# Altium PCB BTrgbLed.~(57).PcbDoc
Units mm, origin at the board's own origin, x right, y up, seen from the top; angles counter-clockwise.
Board outline 98.71 x 98.67 mm, 2 copper layers (Top Layer, Bottom Layer); 15 components, 12 nets, 66 pads, 4 vias.
Unrouted connection lines stored in the file: 35.
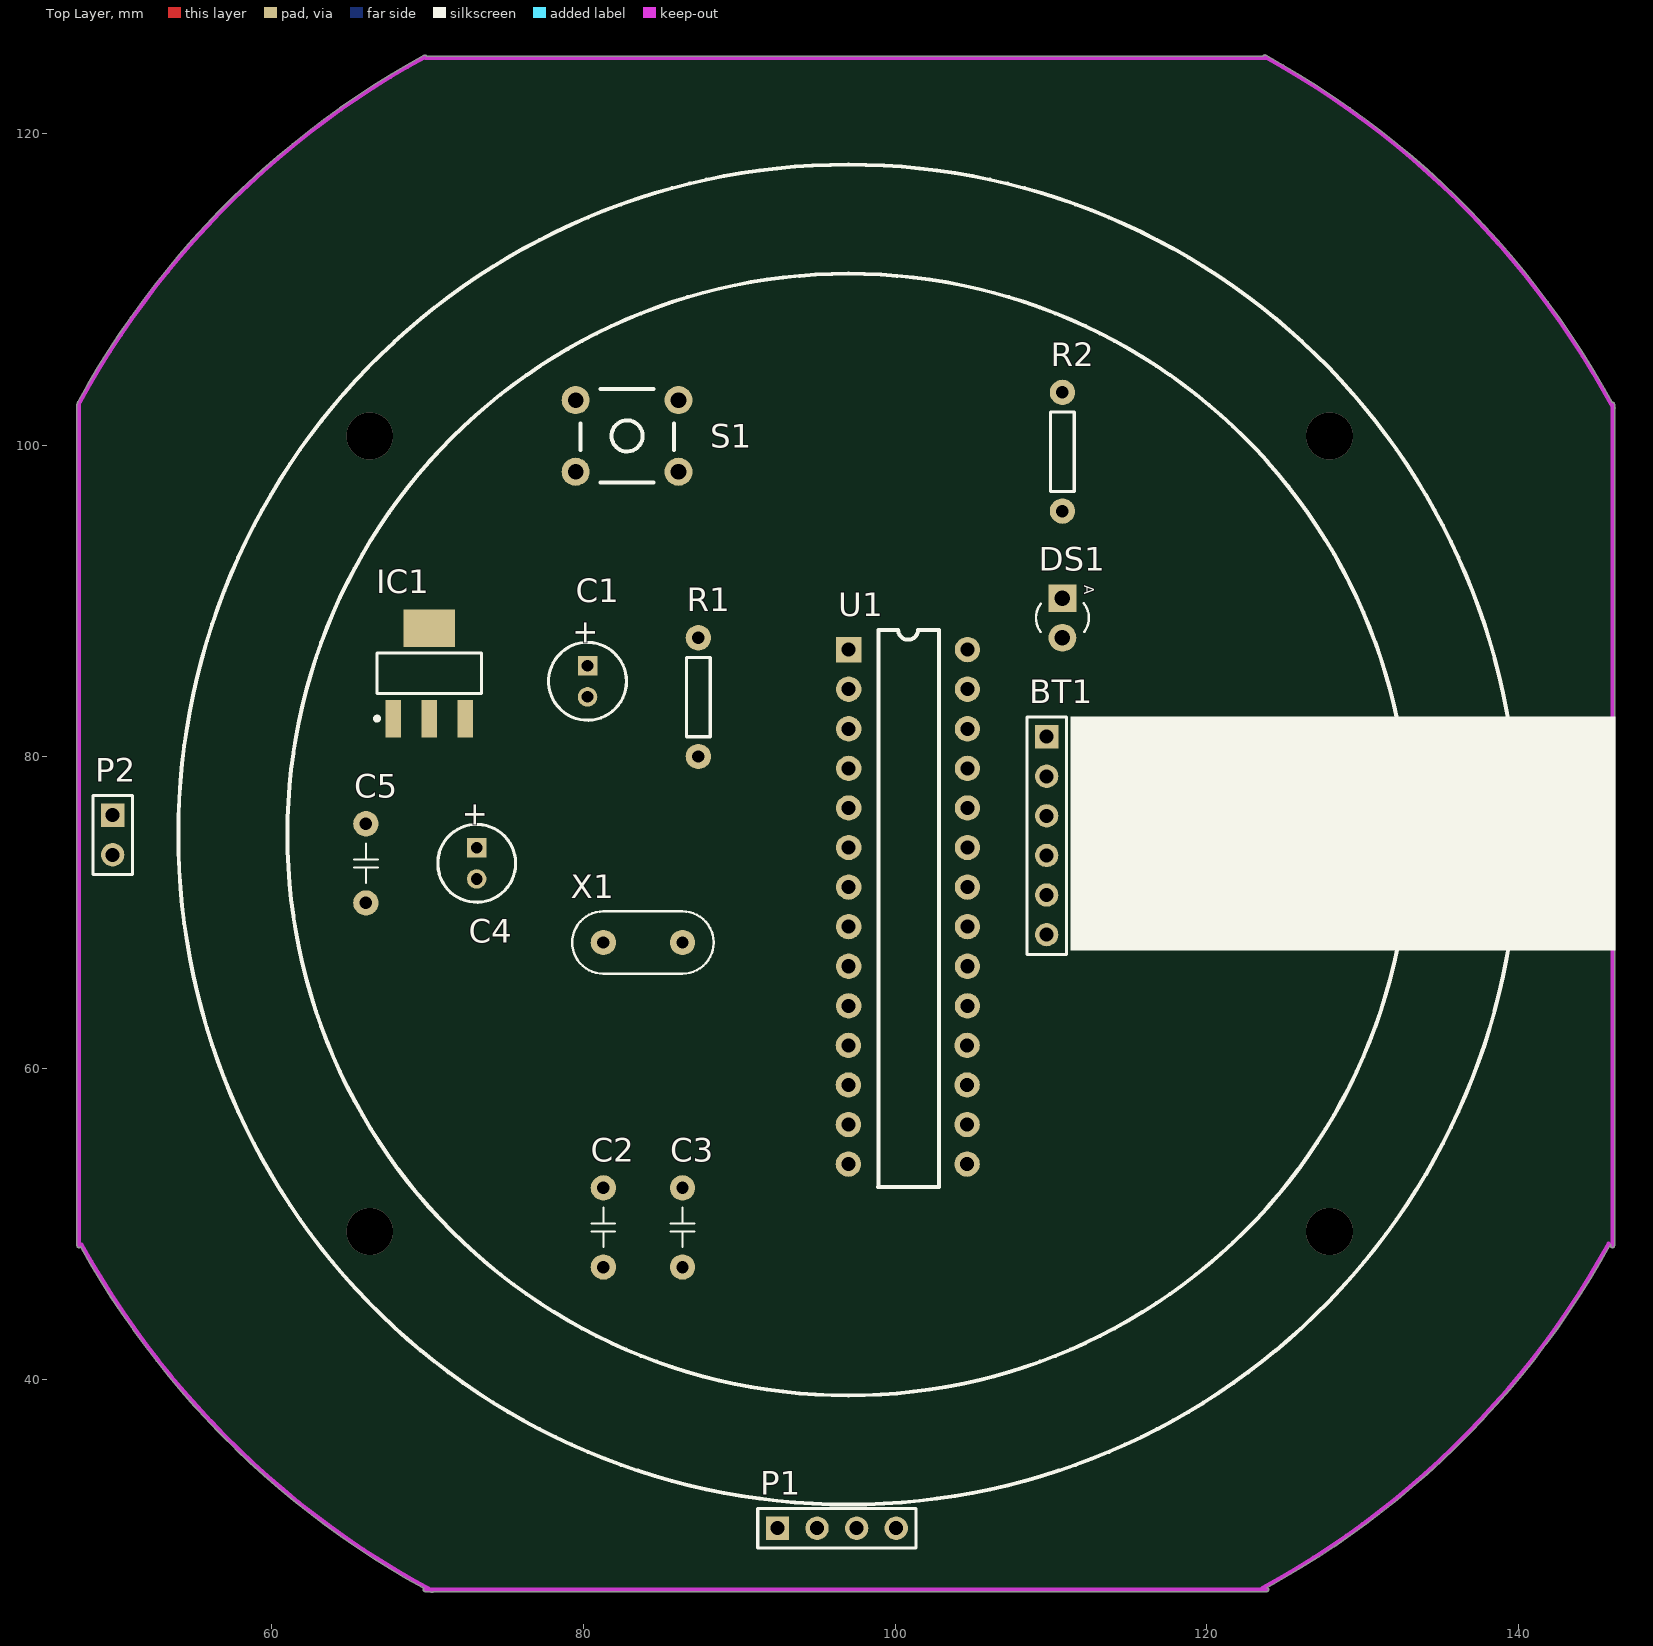
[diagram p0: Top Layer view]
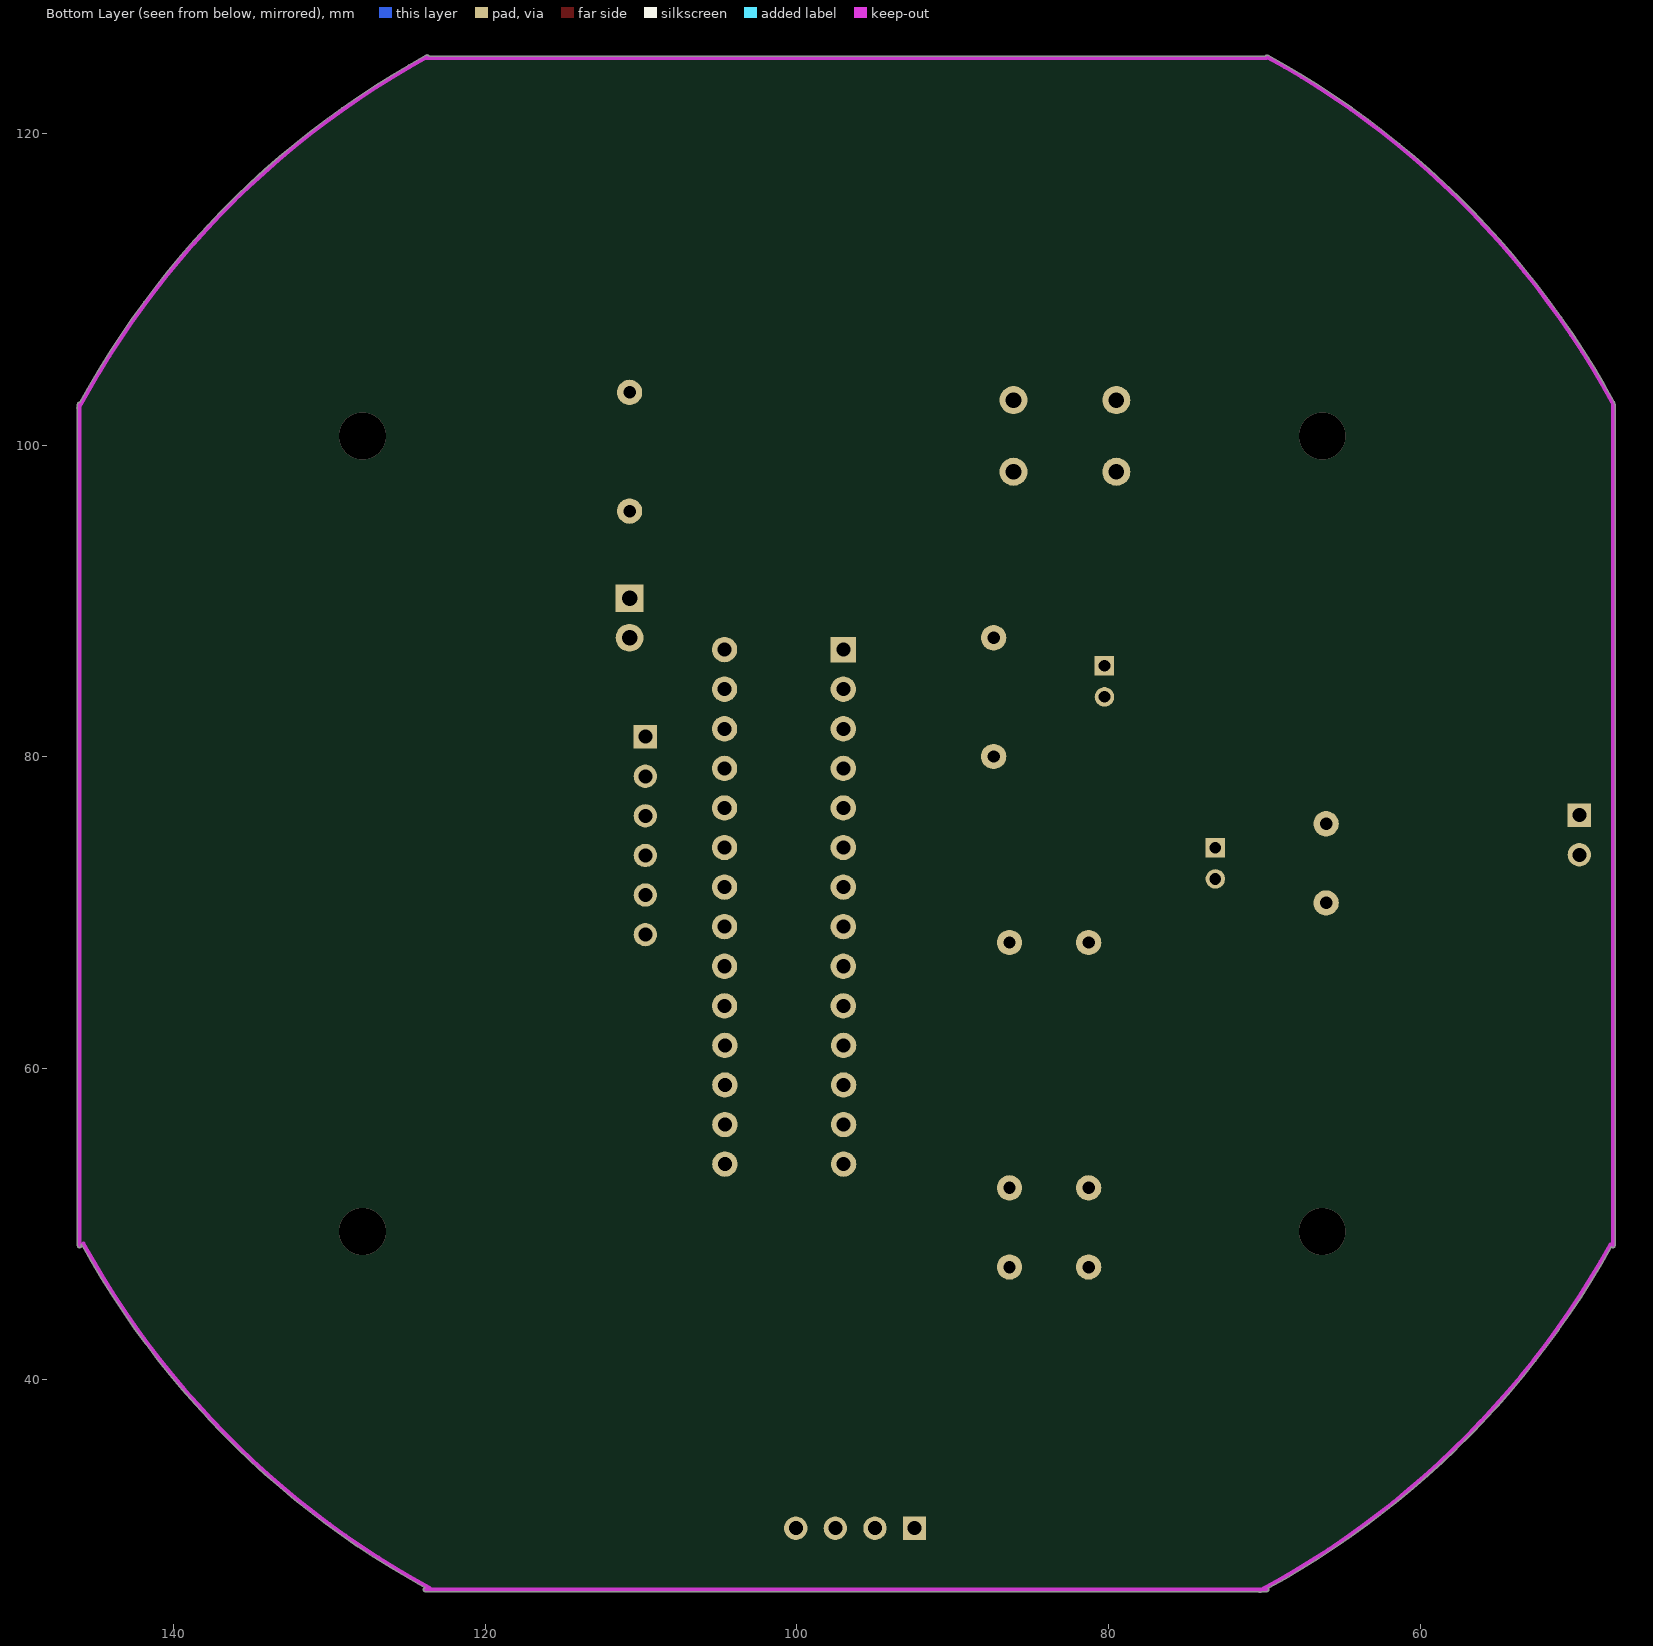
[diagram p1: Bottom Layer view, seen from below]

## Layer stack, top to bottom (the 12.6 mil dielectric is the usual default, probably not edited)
Top Layer: signal copper 0.0356
Dielectric: dielectric 0.32, FR-4, Dk 4.8
Bottom Layer: signal copper 0.0356

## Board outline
69.85,26.416 70.143,26.416 ccw(c96.781,75.819) 70.218,26.375 ccw(c70.279,26.487) 70.384,26.416 123.85,26.416 ccw(c123.85,26.543) 123.977,26.543 ccw(c123.85,26.543) 123.88,26.667 ccw(c96.781,75.819) 145.916,48.69 ccw(c145.805,48.751) 145.923,48.703 145.923,48.616 ccw(c146.05,48.616) 146.177,48.616 146.177,102.295 ccw(c146.082,102.379) 146.209,102.379 ccw(c146.082,102.379) 146.194,102.44 ccw(c96.781,75.819) 146.177,102.47 146.177,102.616 ccw(c146.05,102.616) 146.03,102.742 ccw(c96.781,75.819) 123.795,125.018 ccw(c123.734,124.906) 123.623,124.968 69.925,124.968 ccw(c69.817,124.9) 69.756,125.012 ccw(c96.781,75.819) 47.559,102.791 ccw(c47.671,102.73) 47.544,102.715 ccw(c47.625,102.616) 47.498,102.616 47.498,48.616 ccw(c47.625,48.616) 47.728,48.541 ccw(c96.781,75.819) 69.754,26.627 ccw(c69.85,26.543)

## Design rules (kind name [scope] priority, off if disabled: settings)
Clearance 舖銅安全間距 [All] p1: gap=0.635
Clearance [All] p2: gap=0.254
PolygonConnect [All] p1: connectstyle=Relief reliefconductorwidth=0.254 reliefentries=4 polygonreliefangle="90 Angle"
RoutingLayers [All] p1: top layer_v5=FALSE bottom layer_v5=TRUE
RoutingVias [All] p1: holewidth=0.711 width=1.27 viastyle="Through Hole" minholewidth=0.711 minwidth=1.27 maxholewidth=0.711 maxwidth=1.27
SilkscreenOverComponentPads [All] p1: minsilkscreentomaskgap=0.254
SolderMaskExpansion [All] p1: expansion=0.102
Width [All] p1: maxlimit=1.016 minlimit=0.508 preferedwidth=0.762
26 further rules are at their usual default settings.

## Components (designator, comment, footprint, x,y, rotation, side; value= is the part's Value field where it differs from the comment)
BT1 "Bluetooth" Bluetooth 109.728,81.28 r270 top
C1 "47uF" CAPPR2-5x6.8 80.264,84.836 r270 top
C2 "22pF" C200 81.28,49.784 r0 top
C3 "22pF" C200 86.36,49.784 r0 top
C4 "47uF" CAPPR2-5x6.8 73.152,73.152 r270 top
C5 "100pF" C200 66.04,73.152 r180 top
DS1 "TX-LED" LED-3mm_G 110.744,88.9 r270 top
IC1 "AM1117-5V" SOT-223 70.104,85.344 r90 top
P1 "環形LED燈" HDR1X4 92.456,30.48 r0 top
P2 "12V" HDR1X2 49.784,76.243 r270 top
R1 "10k" AXIAL-0.3 87.376,83.82 r90 top
R2 "220" AXIAL-0.3 110.744,99.568 r90 top
S1 "SW-PB" TACK6 82.804,100.584 r180 top
U1 "ATmega328" DIP-28 97.028,86.868 r270 top
X1 "16MHz" XTAL4-8 83.82,68.072 r180 top

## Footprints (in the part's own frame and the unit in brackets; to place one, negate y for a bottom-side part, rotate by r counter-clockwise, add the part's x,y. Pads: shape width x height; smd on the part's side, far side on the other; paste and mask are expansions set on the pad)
AXIAL-0.3 [mil] "0.3\" Resistor; 2 Leads"
  round 64 hole 31.5: 1(-150,0) 2(150,0)
  silkscreen extent -100,-30 100,30, body extent -161,-39 165,39, height 86
Bluetooth [mm]
  rect 1.5x1.5 hole 0.9: 1(0,0)
  round 1.5 hole 0.9: 2(2.54,0) 3(5.08,0) 4(7.62,0) 5(10.16,0) 6(12.7,0)
  silkscreen extent -1.27,-1.27 13.97,1.27, body extent -1.25,-1.3 13.97,1.28, height 11
C200 [mil] "塑膠電容器"
  round 64 hole 31.5: 1(0,100) 2(0,-100)
  silkscreen extent -30,-50 30,50, body extent -41,-136 39,135, height 354
CAPPR2-5x6.8 [mm] "Capacitor, Electrolytic, Radial; Body 5 x 6.8 mm (Dia.xH typ); Pin Spacing 2 mm (typ)"
  rect 1.25x1.25 hole 0.75: 1(-1,0)
  round 1.25 hole 0.75: 2(1,0)
  silkscreen extent -2.5,-2.5 2.5,2.5
DIP-28 [mil]
  rect 64x64 hole 35.43: 1(0,0)
  round 64 hole 35.43: 2(100,0) 3(200,0) 4(300,0) 5(400,0) 6(500,0) 7(600,0) 8(700,0) 9(800,0) 10(900,0) 11(1000,-0.79) 12(1100,-0.79) 13(1200,-0.79) 14(1300,-0.79) 15(1300,299.21) 16(1200,299.21) 17(1100,299.21) 18(1000,299.21) 19(900,300) 20(800,300) 21(700,300) 22(600,300) 23(500,300) 24(400,300) 25(300,300) 26(200,300) 27(100,300) 28(0,300)
  silkscreen extent -50,74 1358,228, body extent -53,-5 1358,304, height 209
HDR1X2 [mm] "Connector; Header; 2 Position"
  rect 1.5x1.5 hole 0.9: 1(0,0)
  round 1.5 hole 0.9: 2(2.54,0)
  silkscreen extent -1.27,-1.27 3.81,1.27
HDR1X4 [mm] "Connector; Header; 4 Position"
  rect 1.5x1.5 hole 0.9: 1(0,0)
  round 1.5 hole 0.9: 2(2.54,0) 3(5.08,0) 4(7.62,0)
  silkscreen extent -1.27,-1.27 8.89,1.27
LED-3mm_G [mil] "3mm LED_Green"
  rect 70x70 hole 39: 1(-50,0)
  round 70 hole 39: 2(50,0)
  silkscreen extent -38,-67 35,67, body extent -66,-68 67,66, height 181
SOT-223 [mm] "SOT223, 4-Leads, Body 6.7x7.3mm (max), Pitch 2.30mm, IPC Medium Density"
  rect 2.4x1 smd: 1(-2.9,2.3) 2(-2.9,0) 3(-2.9,-2.3)
  rect 2.4x3.3 smd: 2(2.9,0)
  silkscreen extent -3.02,-3.35 1.3,3.47, body extent -1.86,-3.35 1.86,3.35, height 1.8
TACK6 [mm]
  round 1.8 hole 1: 1(-3.3,2.3) 1(3.3,2.3) 2(-3.3,-2.3) 2(3.3,-2.3)
  silkscreen extent -3,-3 3,3, body extent -3,-3.01 3.08,3.04, height 8
XTAL4-8 [mil]
  round 64 hole 31.5: 1(-100,0) 2(100,0)
  silkscreen extent -179,-79 179,79, body extent -178,-80 192,79, height 157

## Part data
C1 C4: library part "Cap Pol1", "Polarized Capacitor (Radial)"
C2 C3 C5: library part Cap, "Capacitor"
DS1: library part LED, "Typical INFRARED GaAs LED"
IC1: library part AM1117
P1: library part "Header 4", "Header, 4-Pin"
P2: library part "Header 2", "Header, 2-Pin"
R1 R2: library part Res, "Resistor"
S1: "Switch"
U1: "Arduino"
X1: library part XTAL, "Crystal Oscillator"

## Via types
v1: diameter 3, hole 3, Top Layer to Bottom Layer, 4 vias

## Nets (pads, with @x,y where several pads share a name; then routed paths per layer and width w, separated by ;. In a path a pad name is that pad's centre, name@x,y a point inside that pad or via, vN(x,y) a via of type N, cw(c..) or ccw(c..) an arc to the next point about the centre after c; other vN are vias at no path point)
DI: P1.1 U1.12
DO: P1.4
GND: BT1.3 C1.2 C2.1 C3.1 C4.2 C5.1 DS1.2 IC1.1 P1.3 P2.2 S1.1 U1.8 U1.22
NetC1_1: C1.1 R1.2 S1.2 U1.1
NetC2_2: C2.2 U1.10 X1.2
NetC3_2: C3.2 U1.9 X1.1
NetDS1_1: DS1.1 R2.1
NetIC1_3: IC1.3 P2.1
NetR2_2: R2.2 U1.19
RX: BT1.5 U1.6
TX: BT1.4 U1.5
VCC: BT1.2 C4.1 C5.2 IC1.2 P1.2 R1.1 U1.7 U1.20
pads on no net: BT1.1 BT1.6 U1.2 U1.3 U1.4 U1.11 U1.13 U1.14 U1.15 U1.16 U1.17 U1.18 U1.21 U1.23 U1.24 U1.25 U1.26 U1.27 U1.28
copper on no net:
  other v1: 66.294,49.53 127.889,49.53 66.294,100.584 127.889,100.584

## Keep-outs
Keep-Out Layer:
  lines w0.254: 47.625,48.616 47.625,102.616 ; 47.671,102.73 cw(c96.781,75.819) 69.817,124.9 ; 47.783,48.704 ccw(c96.781,75.819) 70.279,26.487 ; 69.85,26.543 123.85,26.543 ; 69.85,124.841 123.85,124.841 ; 123.584,26.65 ccw(c96.781,75.819) 145.805,48.751 ; 123.734,124.906 cw(c96.781,75.819) 146.082,102.379 ; 146.05,48.616 146.05,102.616

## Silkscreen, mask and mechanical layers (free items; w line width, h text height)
Top Overlay:
  circle w0.254: c97,75 r36
  circle w0.254: c97,75 r43
  region: 146.252,67.564 146.252,82.564 111.252,82.564 111.252,67.564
